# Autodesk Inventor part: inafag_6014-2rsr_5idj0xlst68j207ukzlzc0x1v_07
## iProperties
Shininess: 64.0
Angle Display Precision: 2
Document Length Units: 11269
Document Angle Units: 11279
Document Time Units: 11290
Document Mass Units: 11283
Document Length Units Precision: 3
Document Angle Units Precision: 2
Compacted: True
Created: 2008-08
Part Number: inafag_6014-2rsr_5idj0xlst68j207ukzlzc0x1v_07
Document SubType Name: Modeling
Designer: tpomodeler
Density: 0.0
Volumn: 0.0
Area: 0.0
PropertySet Name: Model Information
Control State: 0
Master: False
Checked Out: False
Author: tpomodeler
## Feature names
1. inafag_6014-2rsr_5idj0xlst68j207ukzlzc0x1v
